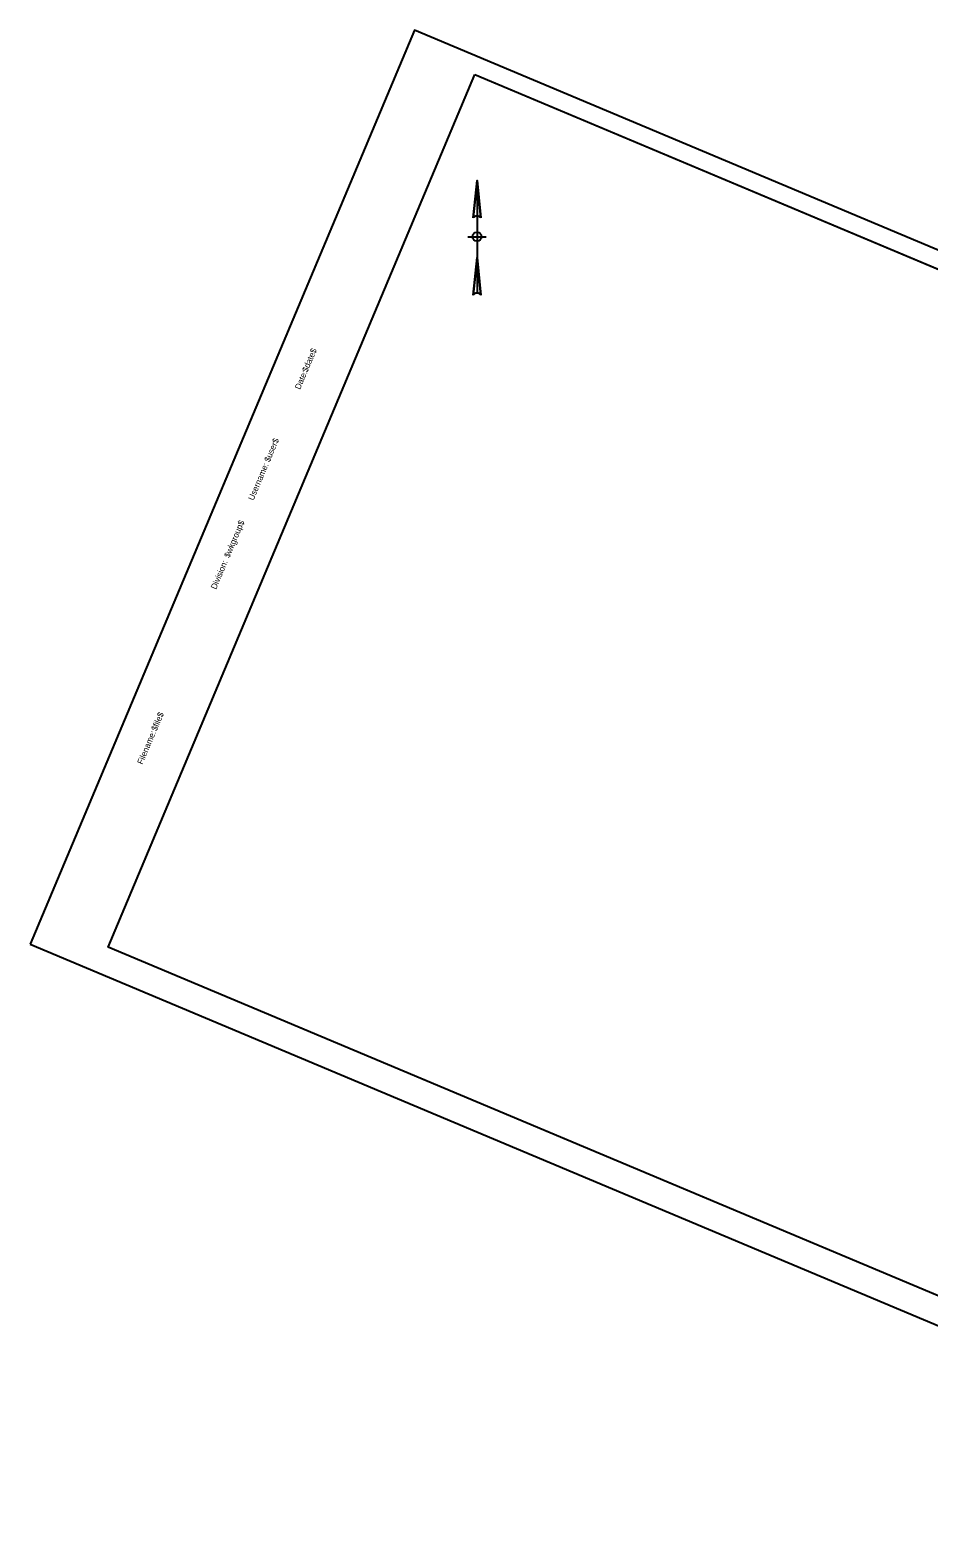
# Model space of a CAD drawing. Extents: x 1745429 to 1746425, y 462900 to 463737.
# Drawn here: x 1745429 to 1745927, y 462900 to 463737 of the extents above; entities that cross this region are included whole.
import ezdxf

# ---------------------------------------------------------------- set-up
doc = ezdxf.new("R2010")
doc.units = 0
for name, color, linetype in [('D_Roadway_Centerline_Text', 7, 'Continuous'), ('D_Text_Standard', 7, 'Continuous'), ('M_Fencing', 7, 'Continuous'), ('M_Misc_MiscItems', 7, 'Continuous')]:
    doc.layers.add(name, color=color, linetype=linetype)

msp = doc.modelspace()

# ---------------------------------------------------------------- linework, layer by layer
at = {"layer": 'D_Roadway_Centerline_Text'}
msp.add_lwpolyline([(1745675.19, 463712.08), (1746412.7, 463402.13), (1746209.29, 462918.14), (1745471.78, 463228.09)], close=True, dxfattribs=at)
at = {"layer": 'D_Text_Standard'}
for p, q in [((1745674.25, 463632.55), (1745676.34, 463653.39)), ((1745676.34, 463653.39), (1745676.34, 463590.89)), ((1745676.34, 463653.39), (1745678.42, 463632.55)), ((1745671.34, 463622.14), (1745681.34, 463622.14)), ((1745674.25, 463589.77), (1745676.34, 463610.6)), ((1745676.34, 463610.6), (1745678.42, 463589.77))]:
    msp.add_line(p, q, dxfattribs=at)
for points in [[(1745678.42, 463632.55), (1745676.34, 463653.39), (1745675.3, 463642.97), (1745674.25, 463632.55)], [(1745678.42, 463589.77), (1745676.34, 463610.6), (1745675.3, 463600.18), (1745674.25, 463589.77)]]:
    msp.add_lwpolyline(points, dxfattribs=at)
msp.add_circle((1745676.34, 463622.14), 2.5, dxfattribs=at)
for centre in [(1745676.34, 463631.17), (1745676.34, 463631.17), (1745676.34, 463588.39), (1745676.34, 463588.39)]:
    msp.add_arc(centre, 2.5, 33.55731, 146.44269, dxfattribs=at)
at = {"layer": 'M_Fencing'}
msp.add_lwpolyline([(1745428.55, 463229.67), (1746212.16, 462900.34), (1746425.25, 463407.38), (1745641.64, 463736.71)], close=True, dxfattribs=at)
at = {"layer": 'M_Misc_MiscItems'}
msp.add_lwpolyline([(1745675.19, 463712.08), (1746366.61, 463421.5), (1746163.2, 462937.51), (1745471.78, 463228.09)], close=True, dxfattribs=at)

# ---------------------------------------------------------------- texts
at = {"layer": 'D_Roadway_Centerline_Text'}
for s, p in [('$date$', (1745582.27, 463546.69)), ('Date:', (1745578.23, 463537.06)), ('$user$', (1745561.32, 463496.84)), ('Username:', (1745552.37, 463475.53)), ('$wkgroup$', (1745539, 463443.73)), ('Division:', (1745531.64, 463426.2)), ('$file$', (1745498.62, 463347.65)), ('Filename:', (1745490.82, 463329.09))]:
    msp.add_text(s, height=3.348, rotation=67.20464, dxfattribs=at).set_placement(p)

doc.saveas('drawing.dxf')
